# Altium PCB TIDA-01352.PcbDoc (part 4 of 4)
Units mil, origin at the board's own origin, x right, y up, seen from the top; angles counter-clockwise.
Board outline 6496.06 x 8661.42 mil, 4 copper layers (Top Layer, GND, PWR, Bottom Layer), stack 79.834 mil thick; 456 components, 240 nets, 1197 pads, 446 vias.
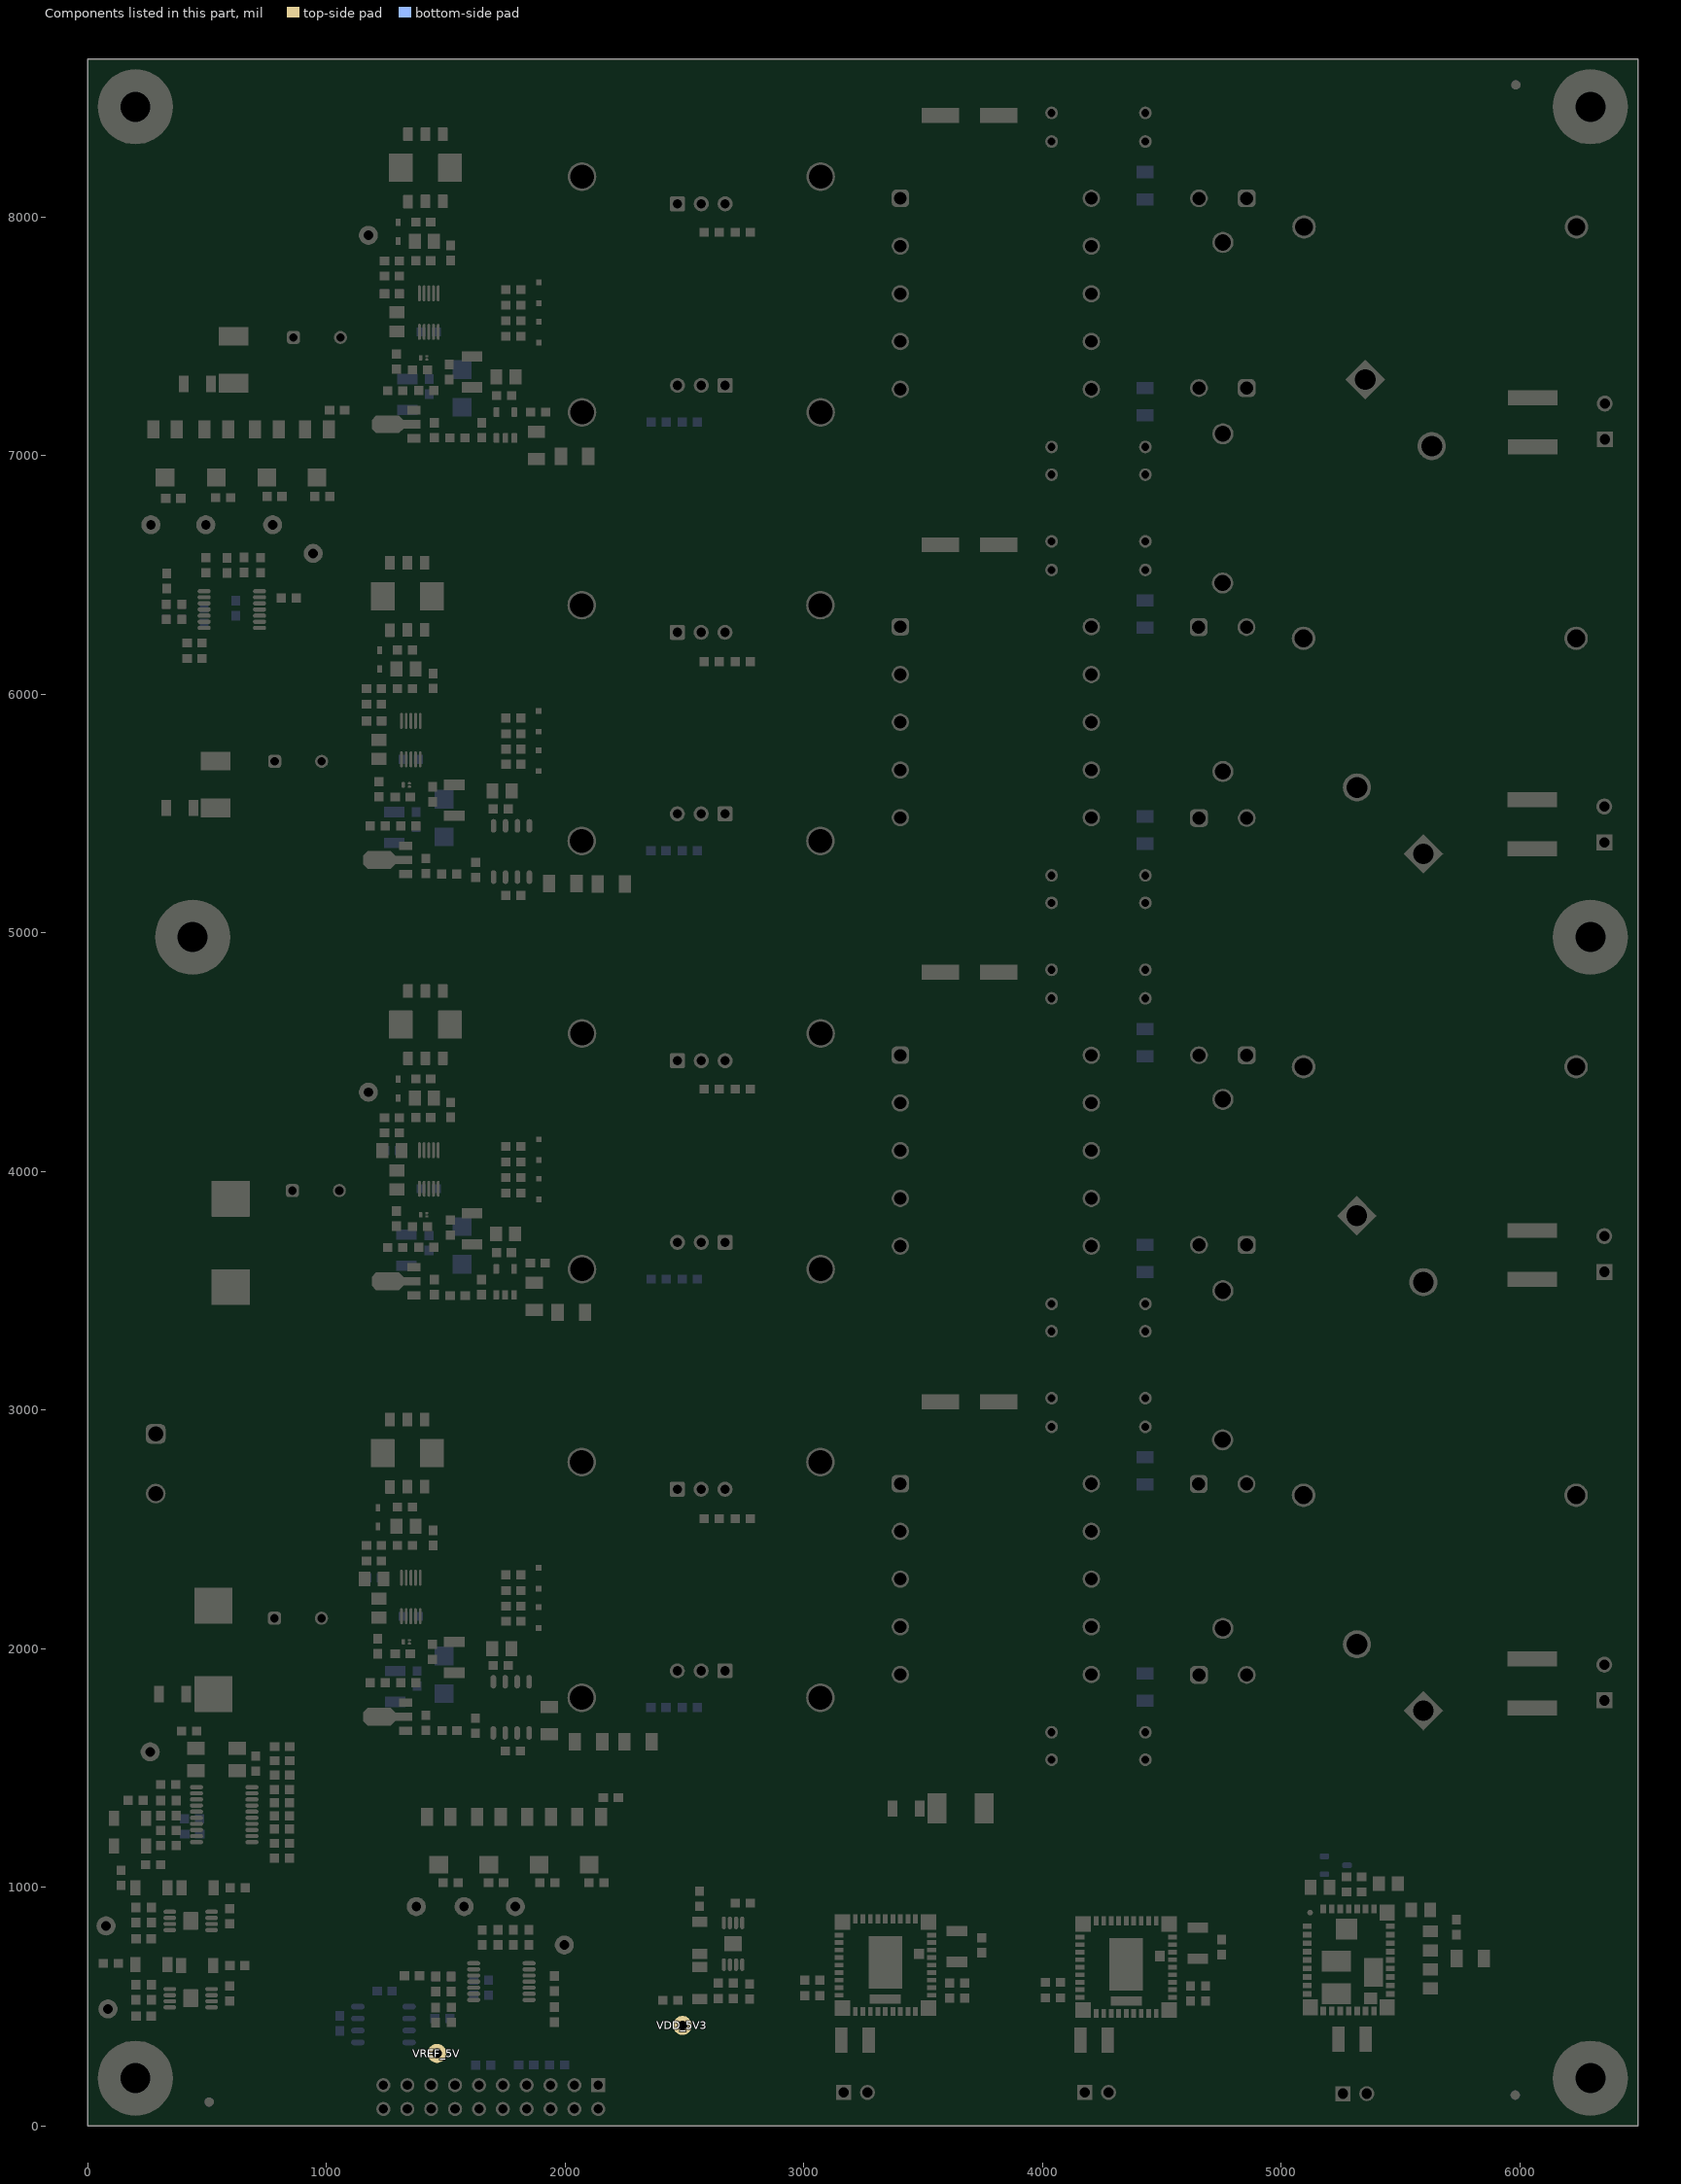
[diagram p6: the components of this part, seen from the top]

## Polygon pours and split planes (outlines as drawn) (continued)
NetC115_2 on Bottom Layer "h" (solid, remove dead copper, pour order 680): 4487.91,1504.5 4487.91,1809.5 4482.91,1814.5 4392.91,1814.5 4387.91,1809.5 4387.91,1504.5 4397.91,1494.5 4477.91,1494.5
GND on Bottom Layer "h" (solid, remove dead copper, pour order 674): 3990,2324.5 3990,1494.5 4000,1484.5 4070,1484.5 4090,1504.5 4090,2149.5 4145,2204.5 4145,2324.5
GND on Bottom Layer "h" (solid, remove dead copper, pour order 666): 3990,4120 3990,3290 4000,3280 4070,3280 4090,3300 4090,3945 4145,4000 4145,4120
NetC120_2 on Bottom Layer "h" (solid, remove dead copper, pour order 652): 4487.91,3300 4487.91,3605 4482.91,3610 4392.91,3610 4387.91,3605 4387.91,3300 4397.91,3290 4477.91,3290
NetC118_1 on Bottom Layer "h" (solid, remove dead copper, pour order 650): 4375,4875 4375,4570 4380,4565 4470,4565 4475,4570 4475,4875 4465,4885 4385,4885
NetC120_1 on Bottom Layer "h" (solid, remove dead copper, pour order 644): 4665,3730 4175,3730 4165,3720 4165,3645 4170,3640 4685,3640 4695,3650 4695,3720 4685,3730
NetC118_2 on Bottom Layer "h" (solid, remove dead copper, pour order 642): 4665,4530 4175,4530 4165,4520 4165,4445 4170,4440 4685,4440 4695,4450 4695,4520 4685,4530
GND on Bottom Layer "h" (solid, remove dead copper, pour order 632): 2490,3665 2404.5,3665 2380,3640.5 2380,3525.46 2375,3520.46 2329.54,3520.46 2325,3525 2325,3715 2340,3730 2350,3740 2490,3740 2500,3740 2505,3735 2505,3670 2500,3665
NetC56_2 on Bottom Layer "h" (solid, remove dead copper, pour order 630): 2510,3590 2405,3590 2400,3585 2400,3530 2400,3525 2405,3520 2510,3520 2515,3525 2515,3585
NetC56_1 on Bottom Layer "h" (solid, remove dead copper, pour order 626): 25 vertices, not listed, extent 2535,3480 3455,3795
GND on Bottom Layer "Top Layer-MU" (solid, remove dead copper, pour order 10): 5085.11,433 5286.11,433 5291.11,428 5291.11,113 5278.11,100 5088.11,100 5078.11,110 5078.11,426
A_VOUT on Bottom Layer "Top Layer-MU" (solid, remove dead copper, pour order 14): 5307.11,426 5307.11,114 5321.11,100 5467.11,100 5480.11,113 5480.11,429 5476.11,433 5311.11,433 5307.11,429
A_VOUT on Bottom Layer "Top Layer-MU" (solid, remove dead copper, pour order 22): 5147.11,876 5142.11,871 5142.11,628 5142.11,498 5157.11,483 5296.11,483 5307.11,472 5307.11,429 5307.11,292 5318.11,281 5471.11,281 5481.11,291 5481.11,867 5472.11,876
GND on Bottom Layer "Top Layer-MU" (solid, remove dead copper, pour order 36): 3968.11,438 4204.11,438 4210.11,432 4210.11,105 4204.11,99 3968.11,99 3961.11,106 3961.11,431
NetC18_1 on Bottom Layer "Top Layer-MU" (solid, remove dead copper, pour order 38): 4247.11,423 4247.11,107.5 4254.61,100 4414.11,100 4425,110.89 4425,430.61 4417.61,438 4251.61,438 4247.11,433.5
GND on Bottom Layer "Top Layer-MU" (solid, remove dead copper, pour order 50): 2959.11,446.73 3195.11,446.73 3201.11,440.73 3201.11,113.73 3195.11,107.73 2959.11,107.73 2952.11,114.73 2952.11,439.73
NetC4_1 on Bottom Layer "Top Layer-MU" (solid, remove dead copper, pour order 52): 3238.11,431.73 3238.11,116.23 3245.61,108.73 3405.11,108.73 3416,119.62 3416,439.34 3408.61,446.73 3242.61,446.73 3238.11,442.23
NetC24_1 on Bottom Layer "Top Layer-MU" (solid, remove dead copper, pour order 70): 1426,687 1426,608 1428,606 1579,606 1595,590 1639,590 1641,592 1641,689 1631,699 1434,699 1426,691
GND on Bottom Layer "Top Layer-MU" (solid, remove dead copper, pour order 74): 1540,584 1351,584 1348,581 1348,543.17 1352.17,539 1549,539 1554,544 1554,581.88 1551.88,584
VREF_5V on Bottom Layer "Top Layer-MU" (solid, remove dead copper, pour order 80): 502.76,6317.3 466.76,6317.3 459.76,6310.3 459.32,6122.74 465.76,6116.3 544.76,6116.3 550.76,6122.3 550.76,6311.3 544.76,6317.3
NetC36_1 on Bottom Layer "Top Layer-MU" (solid, remove dead copper, pour order 84): 296.77,6437.07 296.77,6358.07 298.77,6356.07 449.77,6356.07 465.77,6340.07 509.77,6340.07 511.77,6342.07 511.77,6439.07 503.54,6447.3 303,6447.3 296.77,6441.07
GND on Bottom Layer "Top Layer-MU" (solid, remove dead copper, pour order 92): 308.76,6332.3 308.76,6122.3 312.76,6118.3 433.76,6118.3 438.76,6123.3 438.76,6324.3 429.76,6333.3 309.76,6333.3 308.76,6332.3
CLK_1.8V on Bottom Layer "Top Layer-MU" (solid, remove dead copper, pour order 494): 24 vertices, not listed, extent 37.28,615 195,1340
GND on Bottom Layer "h" (solid, remove dead copper, pour order 598): 1410,3690 1370,3650 1350,3650 1290,3650 1280,3640 1280,3570 1290,3560 1291,3559 1623,3559 1626,3562 1626,3679 1615,3690
GND on Bottom Layer "h" (solid, remove dead copper, pour order 608): 1363.46,1861.53 1323.46,1821.54 1303.46,1821.54 1243.46,1821.54 1233.46,1811.54 1233.46,1741.54 1243.46,1731.54 1244.46,1730.54 1530.54,1730.54 1538,1738 1538,1849 1525.47,1861.53
GND on Bottom Layer "h" (solid, remove dead copper, pour order 614): 1359.57,5460.74 1319.57,5420.74 1299.57,5420.74 1239.57,5420.74 1229.57,5410.74 1229.57,5340.74 1239.57,5330.74 1240.57,5329.74 1526.64,5329.74 1534.1,5337.2 1534.1,5448.2 1521.57,5460.74
GND on Bottom Layer "h" (solid, remove dead copper, pour order 616): 1414.57,7275.74 1374.57,7235.74 1354.57,7235.74 1294.57,7235.74 1284.57,7225.74 1284.57,7155.74 1294.57,7145.74 1295.57,7144.74 1627.57,7144.74 1630.57,7147.74 1630.57,7264.74 1619.57,7275.74
VIN1 on Bottom Layer "h" (solid, remove dead copper, pour order 784): 1326.26,984.63 1330.89,980 1385,980 2595,980 2610,995 2610,1040 2600,1050 2595.37,1054.63 2301.26,1054.63 1334.37,1054.63 1326.26,1046.52
VIN on Bottom Layer "h" (solid, remove dead copper, pour order 790): 23 vertices, not listed, extent 218,1257 3421,1881
GND on Bottom Layer "h" (solid, remove dead copper, pour order 958): 17 vertices, not listed, extent 3999.56,5236 6409.56,6690.5
GND on Bottom Layer "h" (solid, remove dead copper, pour order 972): 17 vertices, not listed, extent 4001.56,6971 6413,8465
VOUT-N1 on PWR "Top Layer-No Net 1" (solid, pour order 1054): 32 vertices, not listed, extent 5251,1899 6408,2701
VOUT-P1 on PWR "Top Layer-No Net 1" (solid, pour order 1050): 30 vertices, not listed, extent 5230,3693 6407.7,4497
NetD3_3 on PWR "h" (solid, remove dead copper, pour order 1046): 4815,2624.5 4815,2719 4838,2742 5079,2742 5148,2673 5148,2008 4973.21,1833.21 4825,1833.21 4810,1848.21 4810,1959.5 4875,2024.5 4875,2564.5
NetD2_1 on PWR "h" (solid, remove dead copper, pour order 1042): 4815,4420 4815,4514.5 4838,4537.5 5079,4537.5 5148,4468.5 5148,3803.5 4973.21,3628.71 4825,3628.71 4810,3643.71 4810,3755 4875,3820 4875,4360
NetD14_3 on PWR "h" (solid, remove dead copper, pour order 1038): 4815,6215.5 4815,6310.01 4838,6333.01 5079,6333.01 5148,6264.01 5148,5599.01 4973.21,5424.22 4825,5424.22 4810,5439.22 4810,5550.5 4875,5615.5 4875,6155.5
VOUT-N2 on PWR "Top Layer-No Net 1" (solid, pour order 1008): 32 vertices, not listed, extent 5251,5494 6408,6292
VOUT-P2 on PWR "Top Layer-No Net 1" (solid, pour order 1002): 31 vertices, not listed, extent 5267,7183 6410,8028
NetC4_1 on PWR "Top Layer-MU" (solid, remove dead copper, pour order 498): 3405.11,108.73 3245.61,108.73 3238.11,116.23 3238.11,547.11 3248,557 3330,557 3425.38,557 3430.69,551.69 3430.69,525.32 3415.91,510.54 3415.91,119.54
NetC18_1 on PWR "Top Layer-MU" (solid, remove dead copper, pour order 500): 4414.11,99 4254,99 4247.11,105.89 4247.11,106.5 4247.11,537.11 4253,543 4440,543 4446,537 4446,510.24 4425,489.24 4425,400 4425,109.89 4414.11,99
A_VOUT on PWR "Top Layer-MU" (solid, remove dead copper, pour order 502): 5147.11,870 5142.11,865 5142.11,622 5142.11,492 5157.11,477 5296.11,477 5307.11,466 5307.11,423 5307.11,286 5318.11,275 5471.11,275 5481.11,285 5481.11,861 5472.11,870
A_VOUT on PWR "Top Layer-MU" (solid, remove dead copper, pour order 532): 5308.11,426 5308.11,114 5322.11,100 5468.11,100 5481.11,113 5481.11,429 5477.11,433 5312.11,433 5308.11,429
NetC118_2 on PWR "h" (solid, remove dead copper, pour order 866): 4665,4530 4175,4530 4165,4520 4165,4445 4170,4440 4685,4440 4695,4450 4695,4520 4685,4530
NetC120_1 on PWR "h" (solid, remove dead copper, pour order 868): 4665,3730 4175,3730 4165,3720 4165,3645 4170,3640 4685,3640 4695,3650 4695,3720 4685,3730
NetC118_1 on PWR "h" (solid, remove dead copper, pour order 870): 4375,4875 4375,4570 4380,4565 4470,4565 4475,4570 4475,4875 4465,4885 4385,4885
NetC120_2 on PWR "h" (solid, remove dead copper, pour order 872): 4487.91,3300 4487.91,3605 4482.91,3610 4392.91,3610 4387.91,3605 4387.91,3300 4397.91,3290 4477.91,3290
NetC125_2 on PWR "h" (solid, remove dead copper, pour order 874): 4487.91,5095.5 4487.91,5400.5 4482.91,5405.5 4392.91,5405.5 4387.91,5400.5 4387.91,5095.5 4397.91,5085.5 4477.91,5085.5
NetC123_1 on PWR "h" (solid, remove dead copper, pour order 876): 4375,6670.5 4375,6365.5 4380,6360.5 4470,6360.5 4475,6365.5 4475,6670.5 4465,6680.5 4385,6680.5
NetC125_1 on PWR "h" (solid, remove dead copper, pour order 878): 4665,5525.5 4175,5525.5 4165,5515.5 4165,5440.5 4170,5435.5 4685,5435.5 4695,5445.5 4695,5515.5 4685,5525.5
NetC123_2 on PWR "h" (solid, remove dead copper, pour order 880): 4665,6325.5 4175,6325.5 4165,6315.5 4165,6240.5 4170,6235.5 4685,6235.5 4695,6245.5 4695,6315.5 4685,6325.5
NetC128_2 on PWR "h" (solid, remove dead copper, pour order 882): 4665,8121.01 4175,8121.01 4165,8111.01 4165,8036.01 4170,8031.01 4685,8031.01 4695,8041.01 4695,8111.01 4685,8121.01
NetC130_1 on PWR "h" (solid, remove dead copper, pour order 884): 4665,7321.01 4175,7321.01 4165,7311.01 4165,7236.01 4170,7231.01 4685,7231.01 4695,7241.01 4695,7311.01 4685,7321.01
NetC128_1 on PWR "h" (solid, remove dead copper, pour order 886): 4375,8466.01 4375,8161.01 4380,8156.01 4470,8156.01 4475,8161.01 4475,8466.01 4465,8476.01 4385,8476.01
NetC130_2 on PWR "h" (solid, remove dead copper, pour order 888): 4487.91,6891.01 4487.91,7196.01 4482.91,7201.01 4392.91,7201.01 4387.91,7196.01 4387.91,6891.01 4397.91,6881.01 4477.91,6881.01
NetC115_2 on PWR "h" (solid, remove dead copper, pour order 890): 4487.91,1504.5 4487.91,1809.5 4482.91,1814.5 4392.91,1814.5 4387.91,1809.5 4387.91,1504.5 4397.91,1494.5 4477.91,1494.5
NetC113_1 on PWR "h" (solid, remove dead copper, pour order 892): 4375,3079.5 4375,2774.5 4380,2769.5 4470,2769.5 4475,2774.5 4475,3079.5 4465,3089.5 4385,3089.5
NetC115_1 on PWR "h" (solid, remove dead copper, pour order 894): 4665,1934.5 4175,1934.5 4165,1924.5 4165,1849.5 4170,1844.5 4685,1844.5 4695,1854.5 4695,1924.5 4685,1934.5
NetC113_2 on PWR "h" (solid, remove dead copper, pour order 896): 4665,2734.5 4175,2734.5 4165,2724.5 4165,2649.5 4170,2644.5 4685,2644.5 4695,2654.5 4695,2724.5 4685,2734.5
VDD_5V3 on PWR "h" (solid, remove dead copper, pour order 2): 1784.41,270.59 1637.41,270.59 1624,284 1624,408 1667,451 1686.59,470.59 1832.59,470.59 2443.54,470.59 2498.54,525.59 2608.54,525.59 2618.54,515.59 2618.54,285.59 2603.54,270.59
VDD_5.3V on PWR "Top Layer-MU" (solid, remove dead copper, pour order 596): 1236,7316 106,7316 35,7245 35,110 100,45 2830,45 2918.01,133.01 2918,1316 2844,1390 1550,1390 1500,1440 1500,7052
NetD20_1 on PWR "h" (solid, remove dead copper, pour order 966): 4815,8017.5 4815,8112.01 4838,8135.01 5079,8135.01 5148,8066.01 5148,7401.01 4973.21,7226.22 4825,7226.22 4810,7241.22 4810,7352.5 4875,7417.5 4875,7957.5
GND on GND "GN" (solid, remove dead copper, pour order 996): 20 vertices, not listed, extent 940.85,6828 6400.85,8510.39
GND on GND "GN" (solid, remove dead copper, pour order 994): 20 vertices, not listed, extent 940,5046 6400,6714.5
GND on GND "GN" (solid, remove dead copper, pour order 992): 20 vertices, not listed, extent 940.85,3241.19 6400.85,4919.38
GND on GND "h" (solid, remove dead copper, pour order 988): 19 vertices, not listed, extent 940.85,7254.9 2907.85,8503.9
GND on GND "h" (solid, remove dead copper, pour order 984): 19 vertices, not listed, extent 940,5459.01 2907,6708.01
GND on GND "h" (solid, remove dead copper, pour order 980): 19 vertices, not listed, extent 940.85,3663.89 2907.85,4912.89
GND on GND "h" (solid, remove dead copper, pour order 978): 19 vertices, not listed, extent 940,1868 2907,3117
GND on GND "GN" (solid, remove dead copper, pour order 806): 20 vertices, not listed, extent 940,1444 6400,3123.5
GND on GND "h" (solid, remove dead copper, pour order 796): 3193,1630 3421,1402 6419,1402 6463,1358 6463,72 6437,46 4622,46 104,46 35,115 35,8551 98,8614 3193,8614

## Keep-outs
Keep-Out Layer:
  lines w10: 20,20 20,8641.42 6468.76,8641.42 6468.76,20 20,20

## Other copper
Top Layer:
  text ".Layer_Name" at 16.11,-1053.94 h35
GND:
  text "GND Layer" at -174.89,-1058 h35
PWR:
  text "PWR Layer" at -108.89,-1055 h35
Bottom Layer:
  text ".Layer_Name" at 16.11,-1053.94 h35

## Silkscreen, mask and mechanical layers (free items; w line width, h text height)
Top Overlay:
  circle w10: c1378.23,2023.36 r5
  circle w10: c1451.1,3813.2 r5
  circle w10: c1378.23,5614.36 r5
  circle w10: c1451.1,7404.2 r5
  circle w10: c3091.11,862 r14.87
  circle w10: c4102.11,853 r13.89
  circle w10: c5059.11,903 r11.7
  circle w10: c1381,3445 r7.21
  circle w10: c1345,1614 r7.21
  circle w10: c1408.32,7071.9 r3.87
  circle w10: c1373.58,5246.1 r3.87
  lines w6: 38,883 38,903 ; 155,613 166,613 ; 244,1428 179,1428 147,1460 ; 262,1463 199,1463 161,1501 161,1696 23,1696 23,1410 257,1410 269,1398 269,1335 ; 276,1135 410,1135 410,1457.76 366.24,1457.76 ; 294.03,500.02 309.37,484.67 309.37,463.63 319,454 360,454 378,436 378,427 ; 302.36,1037.27 309.27,1037.27 328,1056 347,1056 ; 308,937 330,937 ; 394.2,6925.9 394.2,6933.9 ; 413,6640 436,6663 436,6682 ; 1075,5939 1099.43,5914.57 1128.31,5914.57 ; 1089,2331 1097.72,2322.28 1112.31,2322.28 ; 1161,4130 1170,4121 1189,4121 ; 1164,7718 1177,7705 1202,7705 ; 1407.85,2553.88 1418.97,2565 1423,2565 ; 1407.85,6144.89 1413.89,6144.89 1426,6157 ; 1485,4347.14 1496.86,4359 1506,4359 ; 1485,7938.15 1503.06,7956.2 1509.1,7956.2 ; 1509,853 1521,865 1521,875 ; 1541.26,1111.63 1541.26,1119.63 ; 1548.37,760.63 1554.37,754.63 1591.37,717.63 1697.37,717.63 1702.37,722.63 1702.37,726.63 ; 1736,875 1755.8,855.2 1755.8,849.98 ; 1780.37,725.63 1789.86,716.14 ; 2674.11,474 2674.11,496 2668.11,490 2681.11,490 2675.11,496 ; 5353,1143 5364.78,1131.22 5364.78,1085.19 ; 147,1460 147,1449 159,1461 158,1460 147,1460 ; 1308.13,2010.16 1308.13,2049.16 1363.13,2049.16 1363.13,2010.16 1308.13,2010.16 ; 1308.13,5601.17 1308.13,5640.17 1363.13,5640.17 1363.13,5601.17 1308.13,5601.17 ; 1381,3800 1436,3800 1436,3839 1381,3839 1381,3800 ; 1381,7391.01 1381,7430.01 1436,7430.01 1436,7391.01 1381,7391.01
  lines w10: 834,7186 359,7186 359,7608.01 359,8122 859.01,8622.01 1373,8622.01 3476,8622.01 6469,8622.01 6469,7316 ; 1150.97,7207.97 1174,7184.94 1174,6621 1097,6544 639,6086 295,5742 295,5271 738,5271 953,5056 4170,5056 5967,5056 6083,5172 6435,5172 6469,5206 6469,5283 ; 6468.76,2026 6468.76,3486 ; 6468.76,5624 6468.76,6969 ; 6469,1687 6469,1428.24 6457.76,1417 2316,1417 2257,1476 2132,1476 1151,1476 911,1716 638,1716 208,1716 208,2080 507,2379 507,4037 1501,5031 3476,5031 5982,5031 6469,4544 6469,3819
  text "PUSH-PULL STAGE_MID/LV" at 2215,8533 h50
  text "+55V Max" at 6119,7379 h40
  text "VOUT-P2" at 6202,7318 h35
  text "GND" at 6214,6934 h35
  text "DANGER" at 5969,6421 h35
  text "HIGH VOLTAGE" at 5890,6362 h35
  text "-55V Max" at 6117,5692 h40
  text "VOUT-N2" at 6193,5628 h35
  text "GND" at 6221,5217 h35
  text "PUSH-PULL STAGE_HV" at 2084,4838 h50
  text "'.PRJ_Number'" at 211,4488 h50
  text "-" at 708,4486 h50
  text "E2" at 777,4486 h50
  text "+155V Max" at 6103,3894 h40
  text "VOUT-P1" at 6216,3828 h35
  text "GND" at 6231,3416 h35
  text "24VDC" at 188,3128 h50
  text "VIN" at 222,3048 h50
  text "DANGER" at 5946,2844 h35
  text "HIGH VOLTAGE" at 5867,2785 h35
  text "GND" at 211,2451 h50
  text "-155V Max" at 6093,2088 h40
  text "VOUT-N1" at 6214,2028 h35
  text "GND" at 6218,1623 h35
  text "GND" at 4069,113 h35 r90
  text "GND" at 5148,111 h35 r90
  text "-5V" at 5479,104 h35 r90
  text "GND" at 3058,91 h35 r90
  text "+5V" at 4392,84 h35 r90
  text "+3.3V" at 3381,71 h35 r90
  text ".Layer_Name" at 16.11,-1053.94 h35
Bottom Overlay:
  text ".Layer_Name" at 16.11,-1053.94 h35
Top Paste:
  text ".Layer_Name" at 16.11,-1053.94 h35
Bottom Paste:
  text ".Layer_Name" at 16.11,-1053.94 h35
Top Solder:
  text ".Layer_Name" at 16.11,-1053.94 h35
  text ".Layer_Name" at 16.11,-1053.94 h35
Bottom Solder:
  text ".Layer_Name" at 16.11,-1053.94 h35
Drill Guide:
  text ".Layer_Name" at 16.11,-1053.94 h35
M1 Board Outline:
  the board outline again, w10
M2 Board Dimensions:
  rectangle: -436.39,-605.95 -61.39,-480.95
  rectangle: -561.39,-480.95 -436.39,-355.95
  lines w7: -561.39,-480.95 438.61,-480.95 ; -436.39,-605.95 -436.39,-355.95 ; -311.39,-605.95 -311.39,-355.95 ; -61.39,-605.95 -61.39,-355.95 ; 188.61,-605.95 188.61,-355.95 ; -561.39,-605.95 -561.39,-355.95 438.61,-355.95 438.61,-605.95 -561.39,-605.95
M3 3D STEP Top:
  text ".Layer_Name" at 16.11,-1053.94 h35
M4 3D STEP Bottom:
  text ".Layer_Name" at 16.11,-1053.94 h35
M5 Assembly Top:
  circle w10: c1395.21,7539.2 r12.26
  circle w10: c1441.1,7404.2 r3.61
  circle w10: c1712.22,7049.14 r11
  circle w10: c1381.1,7039.2 r8.25
  circle w10: c1300.21,5747.2 r12.08
  circle w10: c1371.1,5614.2 r3.61
  circle w10: c1346.21,5215.2 r8
  circle w10: c2136.26,169.63 r15.81
  circle w10: c1308.13,2164.01 r10.2
  circle w10: c1371.39,2020 r3.61
  circle w10: c1342.93,1630 r7.07
  circle w10: c1715,3460 r9.22
  circle w10: c1380.97,3444.3 r7.95
  circle w10: c1441.39,3810 r3.61
  circle w10: c1381.87,3957.5 r7.46
  circle w10: c2670,1907.26 r24.45
  circle w10: c2470,2671.26 r24.45
  circle w10: c4657,1891.26 r24.45
  circle w10: c4654,2686.26 r24.45
  circle w10: c4853,3686.26 r24.45
  circle w10: c4849,4484.26 r24.45
  circle w10: c2473,4468.26 r24.45
  circle w10: c2673,3700.26 r24.45
  circle w10: c2475,6256.26 r24.45
  circle w10: c2677,5498.26 r24.45
  circle w10: c4654,5484.26 r24.45
  circle w10: c4650,6289.26 r24.45
  circle w10: c4852,7278.26 r24.45
  circle w10: c4860,8082.26 r24.45
  circle w10: c2474,8063.26 r24.45
  circle w10: c2670,7300.26 r24.45
  lines w6: 85,415 85,425 ; 1289.13,2247.01 1415.05,2247.01 1415.05,2184.02 1291.13,2184.02 1291.13,2245 ; 1290.21,5836.2 1290.21,5773.2 1418.21,5773.2 1418.21,5837.2 1291.21,5837.2 ; 1365.21,7630.2 1493.21,7630.2 1493.21,7566.2 1366.21,7566.2 1366.21,7629.2 ; 1365,3977.01 1365,4040 1490.98,4040 1490.98,3977.01 1365,3977.01
  lines w10: -852.89,-1125.62 5747.11,-1125.62 ; -852.89,-922.28 5749.11,-922.28 ; -852.89,-718.95 -852.89,-1328.95 3152.11,-1328.95 5749.11,-1328.95 5749.11,-718.95 -852.39,-718.95 -852.39,-1328.95 723.11,-1328.95 ; 1612.11,-1328.95 1612.11,-718.95 ; 2879.11,-922.28 2879.11,-718.95 ; 3719.11,-922.28 3719.11,-718.95 ; 4341.11,-1335.45 4341.11,-1132.62
  text "COMPONENTS MARKED 'DNP' SHOULD NOT BE POPULATED." at 592.61,-513.95 h30
  text "ASSEMBLY VARIANT:" at 592.11,-629.45 h30
  text ".VariantName" at 1628.11,-629.45 h30
  text "PCB VIEWED FROM TOP SIDE" at -789.39,-851.12 h30
  text "BOARD #:" at 1687.11,-851.12 h30
  text ".PRJ_Number" at 2232.61,-851.12 h30
  text "REV:" at 3077.11,-851.12 h30
  text "E2" at 3368.61,-851.12 h30
  text "SVN REV:" at 3915.11,-851.12 h30
  text ".VersionControl_RevNumber" at 4421.11,-851.12 h30
  text "TID #:" at 1687.11,-1046.12 h30
  text ".PRJ_Number" at 1872.61,-1051.12 h30
  text "LAYER NAME =" at -789.39,-1053.94 h30
  text "'.Layer_Name'" at -236.89,-1054 h30
  text "PLOT NAME =" at -789.39,-1259.78 h30
  text ".plot_File_Name" at 16.11,-1259.78 h30
  text "GENERATED    :" at 1689.11,-1259.78 h30
  text ".Print_Date" at 2558.61,-1259.78 h30
  text ".Print_Time" at 3287.61,-1259.78 h30
  text "TEXAS INSTRUMENTS" at 4552.11,-1259.78 h30
M6 Assembly Bottom:
  lines w10: -853.39,-922.78 5748.61,-922.78 ; -851.39,-1126.12 5748.61,-1126.12 ; 554.61,-1335.95 554.61,-1133.12 ; 1176.61,-922.78 1176.61,-719.45 ; 2016.61,-922.78 2016.61,-719.45 ; 3283.61,-1329.45 3283.61,-719.45 ; 4172.61,-1329.45 5748.11,-1329.45 5748.11,-719.45 -853.39,-719.45 -853.39,-1329.45 1743.61,-1329.45 5748.61,-1329.45 5748.61,-719.45
  text "COMPONENTS MARKED 'DNP' SHOULD NOT BE POPULATED." at 5541.11,-513.45 h30
  text ".VariantName" at 4497.11,-629.45 h30
  text "ASSEMBLY VARIANT:" at 5536.11,-629.45 h30
  text ".VersionControl_RevNumber" at 474.61,-851.62 h30
  text "SVN REV:" at 980.61,-851.62 h30
  text "E2" at 1527.11,-851.62 h30
  text "REV:" at 1818.61,-851.62 h30
  text "BOARD #:" at 3208.61,-851.62 h30
  text "PCB VIEWED FROM BOTTOM SIDE" at 5685.11,-851.62 h30
  text ".PRJ_Number" at 2739.11,-854.45 h30
  text "'.Layer_Name'" at 5175,-1030 h30
  text "LAYER NAME =" at 5679.39,-1033.94 h30
  text "TID #:" at 3179.11,-1051.12 h30
  text "IGNORE ->" at 1986.96,-1053.94 h30
  text ".PRJ_Number" at 2993.61,-1056.12 h30
  text "TEXAS INSTRUMENTS" at 343.61,-1260.28 h30
  text ".Print_Time" at 1608.11,-1260.28 h30
  text ".Print_Date" at 2337.11,-1260.28 h30
  text "GENERATED    :" at 3206.61,-1260.28 h30
  text ".plot_File_Name" at 4879.61,-1260.28 h30
  text "PLOT NAME =" at 5685.11,-1260.28 h30
M9 Title Sheet:
  lines w10: -1052.39,846.05 -852.39,846.05 ; -1052.39,3221.05 -852.39,3221.05 ; -1052.39,5596.05 -852.39,5596.05 ; -1052.39,11110.61 -1052.39,7971.05 -1052.39,-1528.95 13947.61,-1528.95 13947.61,7971.05 13947.61,11110.61 ; -1052,11111 13948,11111 ; -852.39,7771.05 -852.39,-1328.95 13747.61,-1328.95 ; -852,7771.44 -852,10911 13748,10911 ; 1447.61,-1528.95 1447.61,-1328.95 ; 1448,10911 1448,11111 ; 3947.61,-1528.95 3947.61,-1328.95 ; 3948,10911 3948,11111 ; 5760.11,-1328.95 5760.11,-718.95 10742.61,-718.95 ; 6447.61,-1528.95 6447.61,-1328.95 ; 6448,10911 6448,11111 ; 8947.61,-1528.95 8947.61,-1328.95 ; 8948,10911 8948,11111 ; 10742.61,-1328.95 10742.61,-718.95 ; 10742.61,-1018.95 13742.61,-1018.95 ; 10742.61,-418.95 13742.61,-418.95 ; 10743.61,175.05 13743.61,175.05 ; 11447.61,-1528.95 11447.61,-1328.95 ; 11448,10911 11448,11111 ; 12247.61,-1318.95 12247.61,-718.95 ; 13742.61,-718.95 10742.61,-718.95 ; 13742.61,-118.95 10742.61,-118.95 ; 13747.22,7771.44 13747.22,10911 ; 13747.61,-128.95 13747.61,-1328.95 ; 13747.61,675.55 10743.61,675.55 10742.61,675.55 10742.61,175.05 10742.61,-118.95 ; 13747.61,846.05 13947.61,846.05 ; 13747.61,3221.05 13947.61,3221.05 ; 13747.61,5596.05 13947.61,5596.05 ; 13747.61,7771.05 13747.61,-1328.95 ; 10742.61,-718.95 10742.61,-118.95
  text "1" at 179.34,10981 h35
  text "2" at 2675,10981 h35
  text "3" at 5164.34,10981 h35
  text "4" at 7671.01,10981 h35
  text "5" at 10170,10981 h35
  text "6" at 12675,10981 h35
  text "A" at -977.39,6698.05 h35
  text "A" at 13822.61,6698.05 h35
  text "B" at -977.39,4318.05 h35
  text "B" at 13822.61,4318.05 h35
  text "C" at -977.39,1943.05 h35
  text "C" at 13822.61,1943.05 h35
  text "PROJECT TITLE:" at 10782.61,82.05 h35
  text "'.PRJ_Title'" at 10785.11,-51 h35
  text "DESIGNED FOR:" at 10782.61,-218.95 h35
  text ".PRJ_Customer" at 10832.61,-358.95 h35
  text "D" at -977.39,-426.95 h35
  text "D" at 13822.61,-426.95 h35
  text "FILE NAME:" at 10782.61,-518.95 h35
  text ".PCB_File_Name_No_Path" at 10832.61,-638.95 h35
  text "Texas Instruments (TI) and/or its licensors do not warrant the accuracy or completeness of this specification" at 5813.11,-800.79 h35
  text "ENGINEER:" at 10782.61,-808.95 h35
  text "LAYOUT BY:" at 12287.61,-808.95 h35
  text "or any information contained therein. TI and/or its licensors do not warrant that this design will meet" at 5768.12,-913.45 h35
  text ".PRJ_Engineer" at 10832.61,-963.94 h35
  text "Avinash N" at 12332.11,-981.6 h35
  text "the specifications, will be suitable for your application or fit for any particular purpose, or will operate in" at 5768.12,-1026.12 h35
  text "ALTIUM DESIGNER VERSION:" at 12287.61,-1118.95 h35
  text "an implementation. TI and/or its licensors do not warrant that the design is production worthy. You should" at 5768.12,-1138.78 h35
  text "completely validate and test your design implementation to confirm the system functionality for your application." at 5813.11,-1251.45 h35
  text ".print_Scale" at 10832.61,-1252.28 h35
  text ".Application_BuildNumber" at 12338.11,-1252.28 h35
  text "1" at 178.95,-1458.95 h35
  text "2" at 2674.61,-1458.95 h35
  text "3" at 5163.95,-1458.95 h35
  text "4" at 7670.62,-1458.95 h35
  text "5" at 10169.61,-1458.95 h35
  text "6" at 12674.61,-1458.95 h35
M10 Fab Notes:
  drawing of 228 lines, arcs and shapes, not listed
  text "DESIGN INFORMATION" at 11820.13,6614.55 h35
  text "(REFER ALSO ARRAY/PANEL PROFILING INFORMATION)" at 11458.57,6452.84 h35
  text "BOARD SIZE" at 10772.57,6448.55 h35
  text "X" at 11740.57,6320.73 h35
  text "220 mm" at 11971.89,6320.73 h35
  text "165 mm" at 11178.11,6314.55 h35
  text "Number of Layers :" at 11175.57,6123.55 h35
  text "4" at 12270.38,6113.55 h35
  text "MIN. TRACK WIDTH:" at 11175.57,5984.55 h35
  text "8" at 12271.81,5984.55 h35
  text "MIL" at 12426.57,5984.55 h35
  text "MIN. CLEARANCE:" at 11175.57,5852.55 h35
  text "MIL" at 12426.57,5852.55 h35
  text "3.937" at 12208.11,5843.55 h35
  text "MIN. VIA PAD SIZE:" at 11175.57,5720.55 h35
  text "19.695" at 12188.11,5721 h35
  text "MIL" at 12426.57,5720.55 h35
  text "EXTERNAL" at 12839.11,5579.55 h35
  text "MINIMUM ANNULAR RING" at 10846.34,5574.56 h35
  text "5.9055 MIL" at 11671.11,5573 h35
  text "PER" at 11046.34,5456.55 h35
  text "IPC-D-275 CLASS 2 LEVEL C" at 11266.34,5456.55 h35
  text "MIL, HOLES" at 12754.57,5344.26 h35
  text "+/-" at 12362.11,5343.55 h35
  text "+/-" at 13216.11,5343.55 h35
  text "REGISTRATION TOLERANCES:" at 10846.34,5338.55 h35
  text "METAL" at 12046.11,5338.55 h35
  text "5" at 12622.31,5338.55 h35
  text "3" at 13455.31,5338.55 h35
  text "MIL" at 13571.57,5338.55 h35
  text "MATERIAL:" at 10771.57,5129.09 h35
  text "FR-4 High Tg" at 11758.01,4988.76 h35
  text "FR-408" at 11192.57,4980.19 h35
  text "OTHER" at 12680.57,4980.19 h35
  text "X" at 11596.11,4977.55 h35
  text "63 MIL (1.6mm) +/-10%" at 11512.67,4817.47 h35
  text "THICKNESS:" at 10846.34,4813.19 h35
  text "X" at 11384.51,4813.19 h35
  text "OTHER" at 12797.57,4813.19 h35
  text "TOLERANCE:" at 10846.34,4655.19 h35
  text "X" at 11685.64,4655.19 h35
  text "ANSI IPC-6012 TYPE 3 CLASS 2" at 11872.59,4655.19 h35
  text "OTHER +/-" at 11872.57,4499.19 h35
  text "BOW & TWIST:" at 10846.34,4342.19 h35
  text "X" at 11685.64,4342.19 h35
  text "ANSI IPC-6012 TYPE 3 CLASS 2" at 11872.59,4342.19 h35
  text "OTHER +/-" at 11872.57,4183.68 h35
  text "COPPER THICKNESS (FINISHED):" at 10771.57,4048.19 h35
  text "1.4MIL (1oz)" at 11651.57,3895.47 h35
  text "2MIL (1.4oz)" at 12418.57,3895.47 h35
  text "2.8MIL (2oz)" at 13145.57,3895.47 h35
  text "OUTER:" at 11128.57,3891.19 h35
  text "X" at 11523.11,3890.55 h35
  text "X" at 11520.11,3746.55 h35
  text "1.4MIL (1oz)" at 11651.57,3738.47 h35
  text "2.8MIL (2oz)" at 12418.57,3738.47 h35
  text "N/A" at 13145.11,3738.84 h35
  text "INNER SIGNAL:" at 10839.49,3734.19 h35
  text "DRILLING:" at 10771.57,3595.19 h35
  text "REFERENCE:" at 10846.34,3478.19 h35
  text "X" at 11494.57,3478.19 h35
  text "AS SHOWN" at 11681.57,3478.19 h35
  text "X" at 12395.57,3478.19 h35
  text "NC_DRILL FILES" at 12532.57,3478.19 h35
  text "PTH MIN COPPER THICKNESS:" at 10846.34,3320.19 h35
  text "X" at 12196.57,3320.19 h35
  text "1MIL" at 12333.57,3320.19 h35
  text "OTHER" at 12830.57,3320.19 h35
  text "BOARD FINISH:" at 10771.57,3161.19 h35
  text "X" at 12380.57,3048.19 h35
  text "SILKSCREEN:" at 10926.79,3043.19 h35
  text "X" at 11875.57,3043.19 h35
  text "TOP" at 12001.57,3043.19 h35
  text "BOTTOM" at 12512.57,3043.19 h35
  text "SILKSCREEN COLOR:" at 10926.79,2876.19 h35
  text "X" at 11874.53,2876.19 h35
  text "WHITE" at 12001.57,2876.19 h35
  text "OTHER" at 12512.57,2876.19 h35
  text "SOLDER RESIST COLOR:" at 10926.79,2706.19 h35
  text "X" at 11494.53,2546.99 h35
  text "GREEN" at 11621.57,2546.99 h35
  text "BLUE" at 12212.57,2546.99 h35
  text "OTHER" at 12750.57,2546.99 h35
  text "IMMERSION GOLD (ENIG)" at 11832.57,2358.47 h35
  text "ENEPIG" at 13170.11,2355.19 h35
  text "SURFACE FINISH:" at 10771.57,2354.19 h35
  text "X" at 11645.62,2354.19 h35
  text "IMM. TIN/SILVER OR EQUIV" at 11101.11,2197.19 h35
  text "OTHER" at 12532.57,2197.19 h35
  text "ARRAY/PANEL:" at 10771.57,2018.19 h35
  text "CUT AND TRIM PER MECH LAYER 1" at 11832.57,2013.9 h35
  text "N.C. ROUTE" at 11832.57,1862.19 h35
  text "X" at 12511.57,1862.19 h35
  text "V. SCORE" at 12698.57,1862.19 h35
  text "CERTIFICATION:" at 10771.57,1725.19 h35
  text "MATERIALS AND WORKMANSHIP FOR ALL PCBS" at 11496.57,1725.19 h35
  text "TO MEET OR EXCEED THE REQUIREMENTS OF:" at 11496.57,1627.19 h35
  text "X" at 11123.07,1490.69 h35
  text "ANSI IPC-A-600F CLASS ->" at 11262.07,1490.69 h35
  text "X" at 12901.13,1490.69 h35
  text "2" at 13020.07,1490.69 h35
  text "1" at 12705.07,1489.19 h35
  text "3" at 13374.07,1489.19 h35
  text "X" at 11125.13,1331.19 h35
  text "UL 94V-0" at 11262.07,1331.19 h35
  text "X" at 11937.13,1331.19 h35
  text "RoHS" at 12074.07,1331.19 h35
  text "OTHER" at 12718.47,1331.19 h35
  text "PER ORDER" at 13115.53,1331.19 h35
  text "X" at 12735,1200 h35
  text "VIA TENTING:" at 11952.11,1193.55 h35
  text "ADDITIONAL REQUIREMENTS:" at 10771.57,1190.19 h35
  text "YES" at 12523.78,1184.47 h35
  text "NO" at 12918.58,1184.24 h35
  text "MICROSECTION:" at 10846.34,1075.19 h35
  text "YES" at 11752.07,1075.19 h35
  text "IMPEDANCE CONTROL:" at 12005.11,1049.55 h35
  text "YES" at 12973.11,1048.55 h35
  text "X" at 13531.11,1041.55 h35
  text "NO" at 13364.58,1031.24 h35
  text "REQUIRED" at 12603.57,903.05 h35
  text "BARE BOARD ELEC. TEST:" at 10836.34,900.19 h35
  text "NONE" at 12142.07,900.19 h35
  text "X" at 12476.57,900.19 h35
  text "PER ORDER" at 13195.57,900.19 h35
  text "MANUFACTURER'S UL:" at 10836.34,743.19 h35
  text "RAIL" at 12002.07,738.9 h35
  text "METAL" at 12493.88,738.9 h35
  text "X" at 12869.11,738.55 h35
  text "SILK" at 13005.57,738.9 h35
M11 Gerber Information:
  lines w8: -852.89,-922.28 5749.11,-922.28 ; 2879.11,-922.28 2879.11,-718.95 ; 3719.11,-922.28 3719.11,-718.95
  lines w10: -852.89,-1125.62 5747.11,-1125.62 ; -852.89,-718.95 -852.89,-1328.95 3152.11,-1328.95 5749.11,-1328.95 5749.11,-718.95 -852.39,-718.95 -852.39,-1328.95 723.11,-1328.95 ; 1612.11,-1328.95 1612.11,-718.95 ; 4341.11,-1335.45 4341.11,-1132.62
  text ".PRJ_Number" at 2153.11,-849 h35
  text "ALL ARTWORK VIEWED FROM TOP SIDE" at -789.39,-851.12 h35
  text "BOARD #:" at 1687.11,-851.12 h35
  text "REV:" at 3077.11,-851.12 h35
  text "E2" at 3368.61,-851.12 h35
  text "SVN REV:" at 3915.11,-851.12 h35
  text ".VersionControl_RevNumber" at 4421.11,-851.12 h35
  text "TID #:" at 1687.11,-1046.12 h35
  text ".PRJ_Number" at 1968.11,-1049 h35
  text "LAYER NAME =" at -789.39,-1053.94 h35
  text "PLOT NAME =" at -789.39,-1259.78 h35
  text ".plot_File_Name" at 16.11,-1259.78 h35
  text "GENERATED    :" at 1689.11,-1259.78 h35
  text ".Print_Date" at 2558.61,-1259.78 h35
  text ".Print_Time" at 3287.61,-1259.78 h35
  text "TEXAS INSTRUMENTS" at 4552.11,-1259.78 h35
M12 Stackup:
  lines w6: 10799.11,7264.55 13349.11,7264.55 ; 10799.11,7368.95 13349.11,7368.95 ; 10739.11,6779.55 ccw(c10773.11,6779.55) 10773.11,6745.55 13375.11,6745.55 ccw(c13375.11,6779.55) 13409.11,6779.55 13409.11,7485.55 ccw(c13375.11,7485.55) 13375.11,7519.55 10773.11,7519.55 ccw(c10773.11,7485.55) 10739.11,7485.55 10739.11,6779.55
  text "Layer Stack Up Detail for: TIDA-01352-E2" at 10767.39,7404.45 h57
  text "Layer" at 10799.11,7329.95 h24
  text "Gerber" at 11694.92,7329.95 h24
  text "Copper" at 12258.44,7329.95 h24
  text "Dielectric" at 12861.15,7329.95 h24
  text "Name" at 10799.11,7281.95 h24
  text "Document" at 11694.92,7281.95 h24
  text "Thickness" at 12258.44,7281.95 h24
  text "Material" at 12861.15,7281.95 h24
  text "Top Solder Mask" at 10814.11,7190.55 h34
  text "(.GTS)" at 11694.92,7188.99 h34
  text "Solder Resist" at 12861.15,7188.99 h34
  text "Top Layer" at 10809.11,7095.55 h34
  text "(.GTL)" at 11694.92,7092.24 h34
  text "1.4mil" at 12258.44,7092.24 h34
  text "FR4-High Tg" at 12890.11,7091.55 h34
  text "GND" at 10809.11,7032.55 h34
  text "FR4-High Tg" at 12889.11,7028.55 h34
  text "1.4mil" at 12257.44,7027.24 h34
  text "(.G1)" at 11695.92,7015.24 h34
  text "1.4mil" at 12256.44,6952.24 h34
  text "FR4-High Tg" at 12889.11,6952.55 h34
  text "PWR" at 10809.11,6948.55 h34
  text "(.G2)" at 11695.92,6943.24 h34
  text "FR4-High Tg" at 12895.11,6866.55 h34
  text "Bottom Layer" at 10804.11,6865.55 h34
  text "(.GBL)" at 11703.11,6861.55 h34
  text "1.4mil" at 12263.11,6855.55 h34
  text "Solder Resist" at 12855.11,6788.55 h34
  text "(.GBS)" at 11700.11,6781.55 h34
  text "Bottom Solder Mask" at 10809.11,6780.55 h34
M13 Component Bodies Top:
  text ".Layer_Name" at 16.11,-1053.94 h35
M14 Component Bodies Bottom:
  text ".Layer_Name" at 16.11,-1053.94 h35
M15 Courtyards Top:
  text ".Layer_Name" at 16.11,-1053.94 h35
M16 Courtyards Bottom:
  text ".Layer_Name" at 16.11,-1053.94 h35
Drill Drawing:
  text ".legend" at 6886,427 h60
  text "DRILL TOLERANCE" at 7232.83,331.07 h35
  text "FOR PTH +/- 3MIL" at 7231.25,262.64 h35
  text "7.874mil drill:+0/-7.874mil" at 7226.11,189.55 h35
  text "12mil drill:+0/-12mil" at 7225.11,124.55 h35
  text "16mil drill:+0/-16mil" at 7225.11,52.55 h35
  text "NOTE : Except 7.874 mil vias , all other vias are tented." at 7207.11,-98.45 h35
  text ".Layer_Name" at 16.11,-1053.94 h35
